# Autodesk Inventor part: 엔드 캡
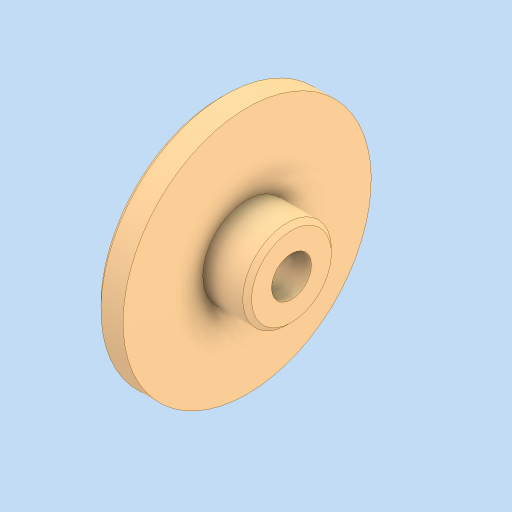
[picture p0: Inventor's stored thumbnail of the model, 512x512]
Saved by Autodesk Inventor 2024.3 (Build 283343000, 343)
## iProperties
Created: 2025-11
Part Number: 엔드 캡
Material: 강철, 연강
Document SubType Name: Modeling
Designer: PC2-02
Density: 7.85 g/cm^3
Appearance: 기본값
Author: jhkim
Sending System: Autodesk Inventor 2026
Preprocessor: ST-DEVELOPER v20.1
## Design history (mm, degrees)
node "엔드 캡1"
node "솔리드2"
node "솔리드1"
